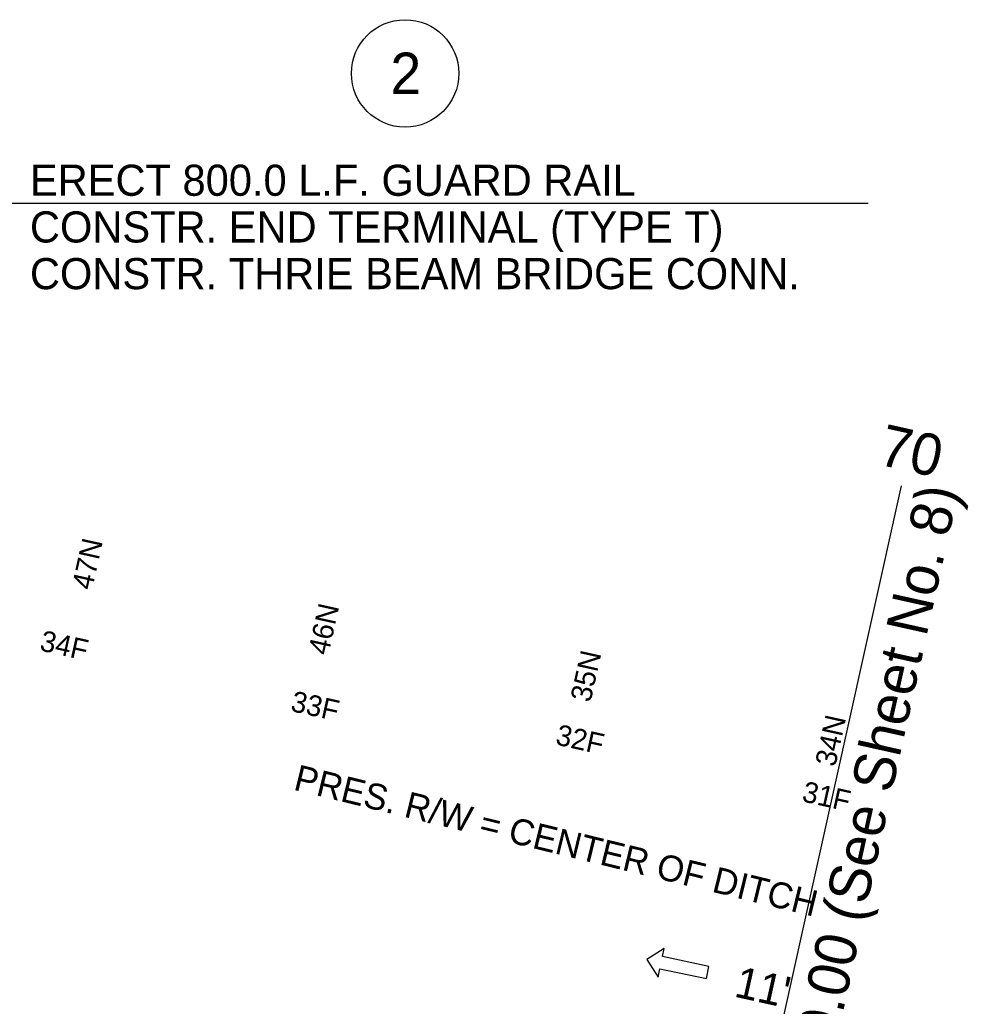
# Model space of a CAD drawing. Extents: x 1964849 to 1967422, y 1116563 to 1122211.
# Drawn here: x 1967169.6 to 1967352.5, y 1118419.5 to 1118609.7 of the extents above; entities that cross this region are included whole.
import ezdxf

# ---------------------------------------------------------------- set-up
doc = ezdxf.new("R2010")
doc.units = 0
for name, color, linetype in [('RD_EX_DV_TX_Prop', 7, 'Continuous'), ('RD_EX_RW_TX', 7, 'Continuous'), ('RD_HC_TX_Sta50', 7, 'Continuous'), ('RD_PD_Final_LnLine', 7, 'Continuous'), ('RD_PD_Final_TX', 7, 'Continuous'), ('RD_PD_TX_CstnLmt', 7, 'Continuous'), ('RD_SHT_MatchLine', 7, 'Continuous'), ('RD_TX_Drainage', 7, 'Continuous'), ('RD_TX_Misc1', 7, 'Continuous')]:
    doc.layers.add(name, color=color, linetype=linetype)

msp = doc.modelspace()

# ---------------------------------------------------------------- linework, layer by layer
at = {"layer": 'RD_EX_DV_TX_Prop'}
msp.add_circle((1967243.94, 1118599.3), 10.35, dxfattribs=at)
at = {"layer": 'RD_PD_Final_LnLine'}
msp.add_lwpolyline([(1967302.03, 1118424.81), (1967302.52, 1118427.15), (1967293.55, 1118429.05), (1967293.89, 1118430.65), (1967290.54, 1118428.47), (1967292.72, 1118425.11), (1967293.05, 1118426.71)], close=True, dxfattribs=at)
at = {"layer": 'RD_SHT_MatchLine'}
msp.add_lwpolyline([(1967294.11, 1118314.83), (1967316.88, 1118417.33), (1967339.66, 1118519.83)], dxfattribs=at)
at = {"layer": 'RD_TX_Misc1'}
msp.add_line((1967333.2, 1118574.21), (1967166.6, 1118574.21), dxfattribs=at)

# ---------------------------------------------------------------- texts
at = {"layer": 'RD_EX_DV_TX_Prop'}
msp.add_text('2', height=8, dxfattribs=at).set_placement((1967241.1, 1118595.31))
at = {"layer": 'RD_EX_RW_TX'}
msp.add_text('PRES. R/W = CENTER OF DITCH', height=5, rotation=346.2938, dxfattribs=at).set_placement((1967222.23, 1118461.26))
at = {"layer": 'RD_HC_TX_Sta50'}
msp.add_text('70', height=8, rotation=347.4724, dxfattribs=at).set_placement((1967334.89, 1118523.96))
at = {"layer": 'RD_PD_Final_TX'}
msp.add_text("11'", height=6, rotation=347.4724, dxfattribs=at).set_placement((1967307.18, 1118421.39))
at = {"layer": 'RD_PD_TX_CstnLmt'}
for s, p in [('34F', (1967173.3, 1118488.11)), ('33F', (1967221.68, 1118476.43)), ('32F', (1967272.76, 1118469.98)), ('31F', (1967320.27, 1118459.02))]:
    msp.add_text(s, height=4, rotation=347.4724, dxfattribs=at).set_placement(p)
at = {"layer": 'RD_SHT_MatchLine'}
msp.add_text('Match Line Sta. 70+00.00 (See Sheet No. 8)', height=8, rotation=77.4724, dxfattribs=at).set_placement((1967305, 1118313.16))
at = {"layer": 'RD_TX_Drainage'}
for s, p in [('47N', (1967183.56, 1118499.56)), ('46N', (1967229.12, 1118487)), ('35N', (1967279.67, 1118477.94)), ('34N', (1967326.86, 1118465.49))]:
    msp.add_text(s, height=4, rotation=77.4724, dxfattribs=at).set_placement(p)
at = {"layer": 'RD_TX_Misc1'}
for s, p in [('ERECT 800.0 L.F. GUARD RAIL', (1967171.6, 1118575.71)), ('CONSTR. END TERMINAL (TYPE T)', (1967171.6, 1118566.71)), ('CONSTR. THRIE BEAM BRIDGE CONN.', (1967171.6, 1118557.71))]:
    msp.add_text(s, height=6, dxfattribs=at).set_placement(p)

doc.saveas('drawing.dxf')
